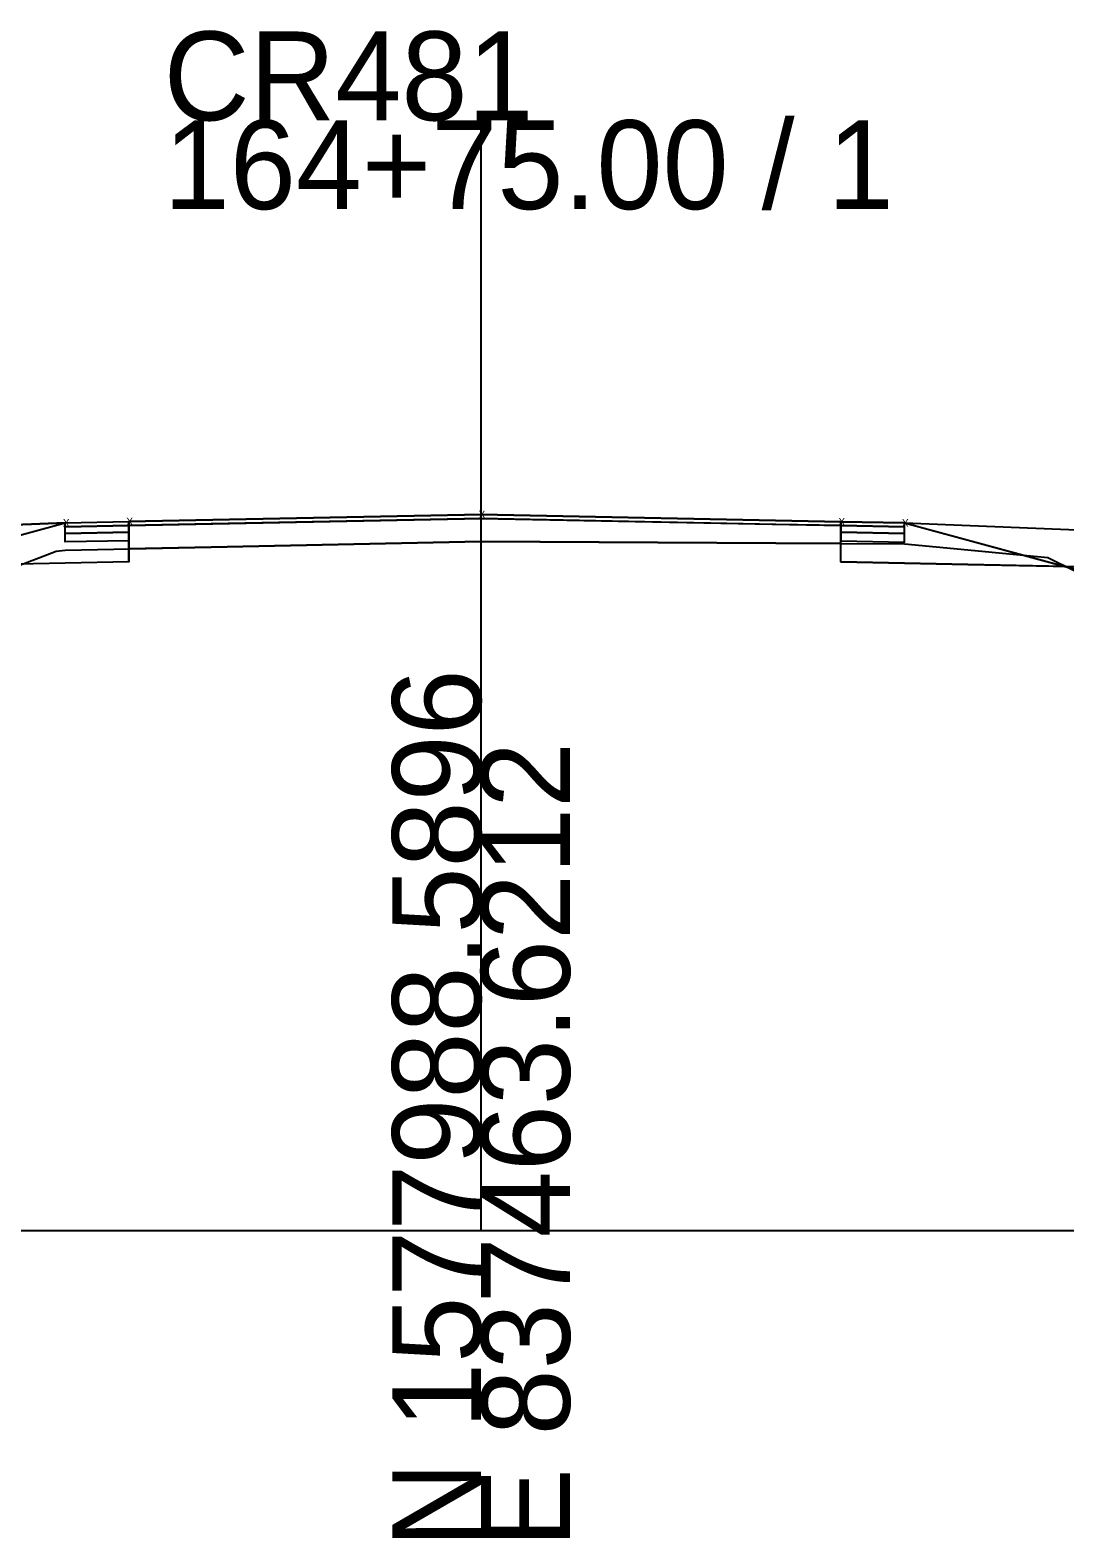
# Model space of a CAD drawing. Extents: x -26 to 303, y -16 to 6048.
# Drawn here: x 135.79 to 168.4, y 2990.31 to 3037.84 of the extents above; entities that cross this region are included whole.
import ezdxf

# ---------------------------------------------------------------- set-up
doc = ezdxf.new("R2010")
doc.units = 0
for name, color, linetype in [('ASPHALT_19MM1', 7, 'Continuous'), ('ASPHALT_9_5MM1', 7, 'Continuous'), ('DTM_P_FINISHED_GRADE2', 7, 'Continuous'), ('DTM_X_GROUND', 7, 'Continuous'), ('TRANS_PAVED_SHOULDERS', 7, 'Continuous'), ('XS_CELL', 7, 'Continuous'), ('XS_M_SHAPES_EARTHWORK', 7, 'Continuous'), ('XS_P_ASPHALT', 7, 'Continuous'), ('XS_P_NULL_POINT', 7, 'Continuous'), ('XS_P_SHOULDER', 7, 'Continuous'), ('XS_P_SUBGRADE_GRANULAR', 7, 'Continuous'), ('XS_P_SUBGRADE_LEVELING', 7, 'Continuous'), ('XS_P_SUBGRADE_MILLING', 7, 'Continuous')]:
    doc.layers.add(name, color=color, linetype=linetype)

msp = doc.modelspace()

# ---------------------------------------------------------------- linework, layer by layer
at = {"layer": 'ASPHALT_19MM1'}
for points in [[(138.898, 3022.016), (138.898, 3021.745), (136.898, 3021.705), (136.898, 3021.976), (138.898, 3022.016)], [(161.342, 3022.012), (161.342, 3021.741), (163.342, 3021.701), (163.342, 3021.972), (161.342, 3022.012)]]:
    msp.add_lwpolyline(points, dxfattribs=at)
at = {"layer": 'ASPHALT_9_5MM1'}
for points in [[(138.898, 3022.35), (138.898, 3022.225), (136.898, 3022.185), (136.898, 3022.31), (138.898, 3022.35)], [(161.342, 3022.345), (161.342, 3022.22), (163.342, 3022.18), (163.342, 3022.305), (161.342, 3022.345)]]:
    msp.add_lwpolyline(points, dxfattribs=at)
at = {"layer": 'DTM_P_FINISHED_GRADE2'}
msp.add_lwpolyline([(100.909, 3012.502), (100.909, 3012.502), (129.436, 3022.011), (136.898, 3022.31), (138.898, 3022.35), (150, 3022.572), (161.342, 3022.345), (163.342, 3022.305), (170.335, 3022.025), (196.584, 3013.275), (199.023, 3012.463)], dxfattribs=at)
at = {"layer": 'DTM_X_GROUND'}
for points in [[(90.987, 3011.993), (100.909, 3012.502), (100.909, 3012.502), (136.898, 3022.31), (136.898, 3022.31), (138.898, 3022.35), (138.898, 3022.35), (150, 3022.572), (161.342, 3022.345), (161.342, 3022.345), (163.342, 3022.305), (163.342, 3022.305), (163.342, 3022.305), (196.361, 3013.35), (196.584, 3013.275), (196.704, 3013.235), (199.023, 3012.463), (199.023, 3012.463), (199.023, 3012.463), (199.023, 3012.463), (199.023, 3012.463), (204.279, 3012.279)], [(90.297, 3011.958), (114.375, 3013.193), (115.641, 3013.245), (117.971, 3014.259), (136.605, 3021.412), (136.898, 3021.446), (141.492, 3021.538), (149.994, 3021.716), (159.289, 3021.672), (163.342, 3021.651), (165.342, 3021.457), (167.862, 3021.214), (170.435, 3019.941), (184.541, 3012.969), (186.717, 3012.893), (193.229, 3012.665), (195.696, 3012.579), (204.279, 3012.279)]]:
    msp.add_lwpolyline(points, dxfattribs=at)
at = {"layer": 'TRANS_PAVED_SHOULDERS'}
for points in [[(138.898, 3022.225), (138.898, 3022.016), (136.898, 3021.976), (136.898, 3022.185), (138.898, 3022.225)], [(161.342, 3022.22), (161.342, 3022.012), (163.342, 3021.972), (163.342, 3022.18), (161.342, 3022.22)]]:
    msp.add_lwpolyline(points, dxfattribs=at)
at = {"layer": 'XS_CELL'}
for p, q in [((150, 3000), (150, 3035)), ((0, 3000), (150, 3000)), ((150, 3000), (300, 3000))]:
    msp.add_line(p, q, dxfattribs=at)
at = {"layer": 'XS_M_SHAPES_EARTHWORK'}
for points in [[(131.865, 3020.938), (136.898, 3022.31), (138.898, 3022.35), (150, 3022.572), (161.342, 3022.345), (163.342, 3022.305), (168.401, 3020.933), (165.342, 3020.994), (163.342, 3021.034), (161.342, 3021.074), (161.342, 3021.661), (159.289, 3021.672), (150, 3021.716), (149.994, 3021.716), (141.492, 3021.538), (138.898, 3021.486), (138.898, 3021.079), (136.898, 3021.039), (134.898, 3020.999)], [(168.401, 3020.933), (196.359, 3013.35), (173.945, 3020.822)]]:
    msp.add_lwpolyline(points, close=True, dxfattribs=at)
at = {"layer": 'XS_P_ASPHALT'}
msp.add_lwpolyline([(138.898, 3022.35), (138.898, 3022.225), (138.898, 3022.225), (150, 3022.447), (161.342, 3022.22), (161.342, 3022.22), (161.342, 3022.345), (161.342, 3022.345), (161.342, 3022.345), (150, 3022.572), (138.898, 3022.35), (138.898, 3022.35), (138.898, 3022.35)], dxfattribs=at)
at = {"layer": 'XS_P_SHOULDER'}
for points in [[(136.898, 3022.31), (129.436, 3022.011)], [(163.342, 3022.305), (170.335, 3022.025)]]:
    msp.add_lwpolyline(points, dxfattribs=at)
at = {"layer": 'XS_P_SUBGRADE_GRANULAR'}
for points in [[(138.898, 3021.079), (138.898, 3022.35)], [(161.342, 3021.074), (161.342, 3022.345)], [(136.898, 3021.039), (134.898, 3020.999), (125.857, 3020.818)], [(138.898, 3021.079), (136.898, 3021.039)], [(161.342, 3021.074), (163.342, 3021.034)], [(163.342, 3021.034), (165.342, 3020.994), (173.945, 3020.822)]]:
    msp.add_lwpolyline(points, dxfattribs=at)
at = {"layer": 'XS_P_SUBGRADE_LEVELING'}
msp.add_lwpolyline([(159.289, 3022.261), (150, 3022.447), (150, 3022.447), (149.994, 3022.447), (149.994, 3022.447), (141.492, 3022.277), (141.492, 3022.277), (138.898, 3022.225), (138.898, 3022.225), (138.898, 3021.486), (141.492, 3021.538), (141.492, 3021.538), (149.994, 3021.716), (149.994, 3021.716), (150, 3021.716), (150, 3021.716), (159.289, 3021.672), (159.289, 3021.672), (161.342, 3021.661), (161.342, 3022.22), (161.342, 3022.22), (159.289, 3022.261), (159.289, 3022.261)], dxfattribs=at)
at = {"layer": 'XS_P_SUBGRADE_MILLING'}
for points in [[(161.342, 3021.661), (159.289, 3021.672), (159.289, 3021.672), (150, 3021.716), (150, 3021.716), (149.994, 3021.716), (149.994, 3021.716), (141.492, 3021.538), (141.492, 3021.538), (138.898, 3021.486)], [(138.898, 3021.486), (141.492, 3021.538), (141.492, 3021.538), (149.994, 3021.716), (149.994, 3021.716), (150, 3021.716), (150, 3021.716), (159.289, 3021.672), (159.289, 3021.672), (161.342, 3021.661)]]:
    msp.add_lwpolyline(points, dxfattribs=at)

# ---------------------------------------------------------------- texts
at = {"layer": 'XS_CELL'}
for s, p in [('CR481', (140, 3035)), ('164+75.00 / 1', (140, 3032.2))]:
    msp.add_text(s, height=2.8, dxfattribs=at).set_placement(p)
for s, p in [('N 1577988.5896', (150, 2990)), ('E 837463.6212', (152.8, 2990))]:
    msp.add_text(s, height=2.8, rotation=90, dxfattribs=at).set_placement(p)
at = {"layer": 'XS_P_NULL_POINT'}
for p in [(136.819, 3022.19), (138.819, 3022.23), (149.922, 3022.452), (161.263, 3022.225), (163.263, 3022.185)]:
    msp.add_text('X', height=0.24, dxfattribs=at).set_placement(p)

doc.saveas('drawing.dxf')
